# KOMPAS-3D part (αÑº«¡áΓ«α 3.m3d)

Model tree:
1. Эскиз:1
2. Операция выдавливания:36
     Толщина стенки 1 = 2; Толщина стенки 2 = 6; Расстояние 1 = 1; Расстояние 2 = 3
3. Эскиз:38
4. Операция выдавливания:40
     Толщина стенки 1 = 2; Толщина стенки 2 = 6; Расстояние 1 = 5; Расстояние 2 = 3
5. Эскиз:39
6. Операция выдавливания:41
     Толщина стенки 1 = 2; Толщина стенки 2 = 6; Расстояние 1 = 1; Расстояние 2 = 3
7. Эскиз:40
8. Операция выдавливания:42
     Толщина стенки 1 = 2; Толщина стенки 2 = 2.5; Расстояние 1 = 50; Расстояние 2 = 3
9. Эскиз:41
10. Вырезать элемент выдавливания:4
     Толщина стенки 2 = 1.5; Расстояние 1 = 40
11. Эскиз:42
12. Операция выдавливания:43
     Толщина стенки 1 = 2; Толщина стенки 2 = 2.5; Расстояние 1 = 50; Расстояние 2 = 3
13. Эскиз:43
14. Вырезать элемент выдавливания:5
     Толщина стенки 2 = 1.5; Расстояние 1 = 40
15. Эскиз:44
16. Операция выдавливания:44
     Толщина стенки 1 = 2; Толщина стенки 2 = 2.5; Расстояние 1 = 10; Расстояние 2 = 3
17. Эскиз:45
18. Эскиз:46
19. Операция выдавливания:47
     Толщина стенки 1 = 2; Толщина стенки 2 = 6; Расстояние 1 = 1; Расстояние 2 = 3
20. Эскиз:47
21. Операция выдавливания:48
     Толщина стенки 1 = 2; Толщина стенки 2 = 6; Расстояние 1 = 5; Расстояние 2 = 3
22. Эскиз:48
23. Операция выдавливания:49
     Толщина стенки 1 = 2; Толщина стенки 2 = 6; Расстояние 1 = 1; Расстояние 2 = 3
24. Эскиз:49
25. Вырезать элемент выдавливания:6
     Толщина стенки 2 = 1.5; Расстояние 1 = 22
26. Эскиз:50
27. Вырезать элемент выдавливания:7
     Толщина стенки 2 = 1.5; Расстояние 1 = 1
28. Эскиз:51
29. Вырезать элемент выдавливания:8
     Толщина стенки 2 = 1.5; Расстояние 1 = 151
30. Эскиз:52
31. Операция выдавливания:50
     Толщина стенки 1 = 2; Толщина стенки 2 = 6; Расстояние 1 = 1; Расстояние 2 = 0.5
